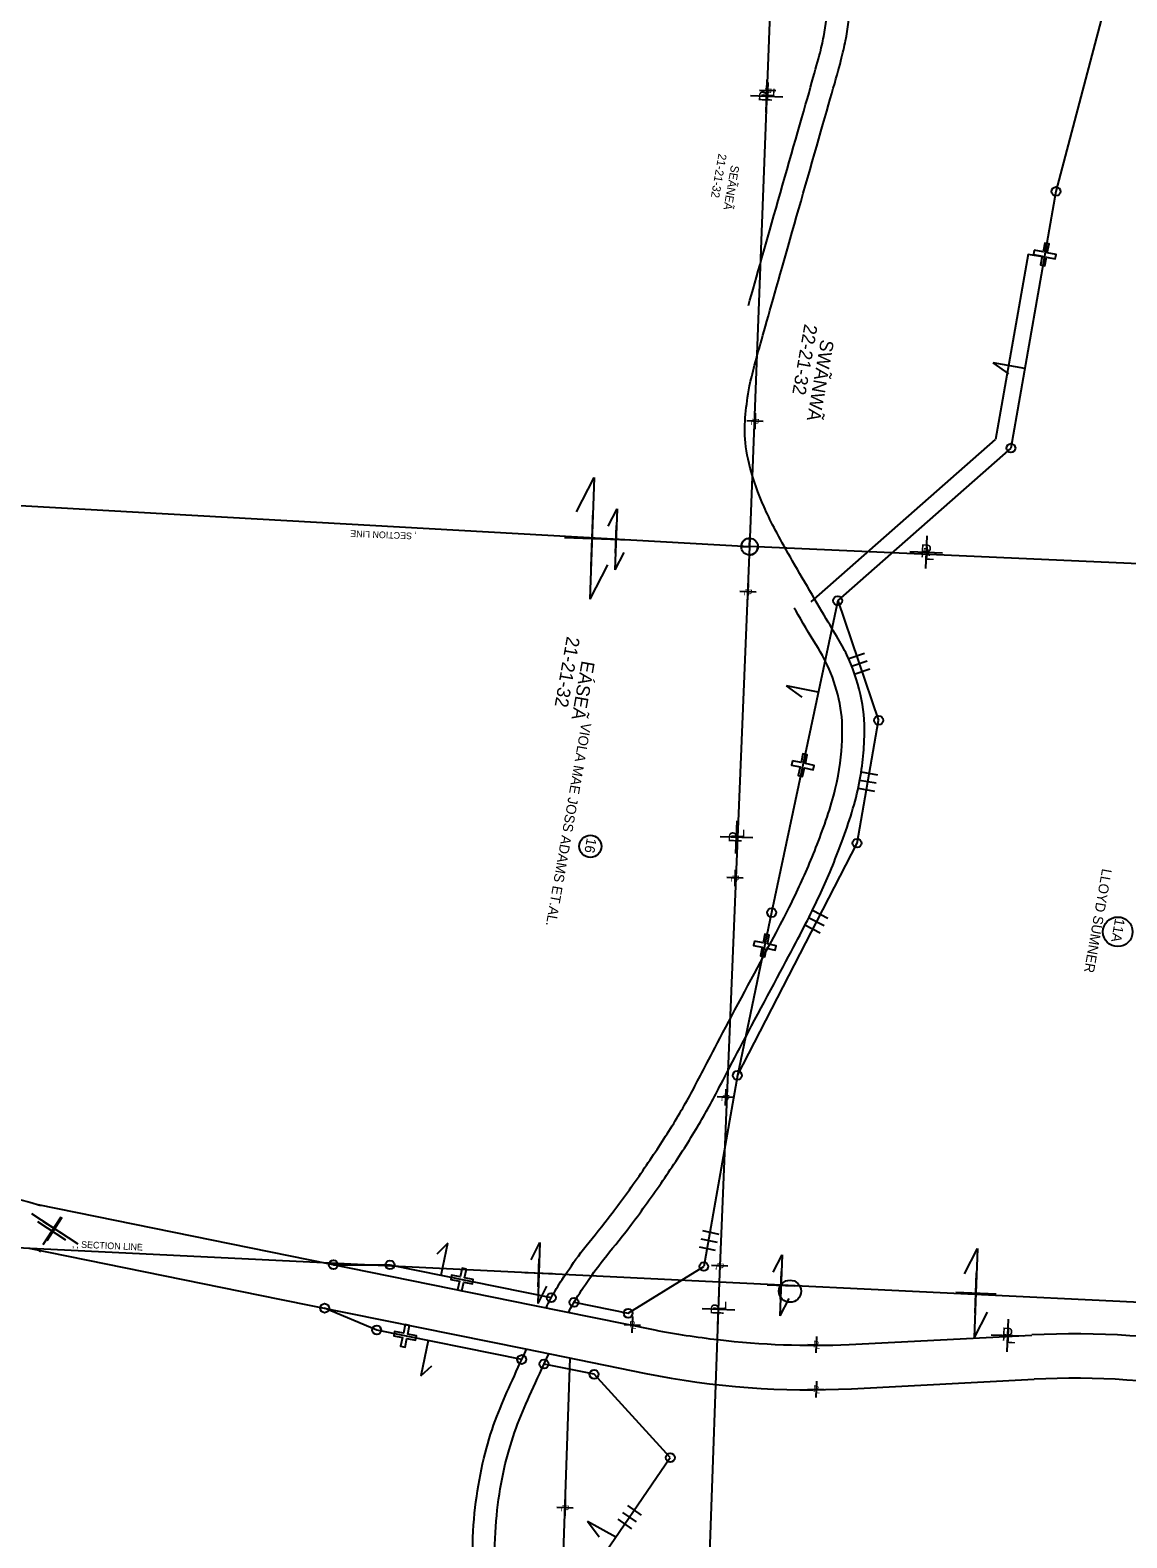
# Model space of a CAD drawing. Extents: x 2814293 to 2835768, y 121185 to 156337.
# Drawn here: x 2819450 to 2821428, y 131914 to 134634 of the extents above; entities that cross this region are included whole.
import ezdxf

# ---------------------------------------------------------------- set-up
doc = ezdxf.new("R2010")
doc.units = 0
for name, color, linetype in [('Default', 7, 'Continuous'), ('Photo-Retaining wall', 7, 'Continuous'), ('Roadway-Alignment notes', 7, 'Continuous'), ('Roadway-Ditches', 7, 'Continuous'), ('Roadway-Edge of pavement', 7, 'Continuous'), ('Roadway-Edge of shoulder', 7, 'Continuous'), ('Roadway-Entrances', 7, 'Continuous'), ('Roadway-New rw', 7, 'Continuous'), ('Roadway-Permanent easement', 7, 'Continuous'), ('Roadway-Safety', 7, 'Continuous'), ('Roadway-Walls', 7, 'Continuous'), ('Scratch-2', 7, 'Continuous'), ('Scratch-4', 7, 'Continuous'), ('Text-New rw label', 7, 'Continuous'), ('Traffic_Control-Traffic barriers', 7, 'Continuous')]:
    doc.layers.add(name, color=color, linetype=linetype)

msp = doc.modelspace()

# ---------------------------------------------------------------- linework, layer by layer
at = {"layer": 'Default'}
for p, q in [((2819451.9, 132499.4), (2819535.8, 132444.9)), ((2819513.9, 132451.6), (2819463.5, 132484.2)), ((2819505, 132493), (2819472.4, 132442.7)), ((2819472.7, 132485.5), (2819514.7, 132458.3)), ((2819480.1, 132450.9), (2819507.3, 132492.9)), ((2819466.6, 132430.2), (2819468.3, 132432.8))]:
    msp.add_line(p, q, dxfattribs=at)
at = {"layer": 'Roadway-Ditches'}
for centre, radius in [((2820460.1, 133161.8), 20), ((2821411.3, 133007.6), 26.7), ((2820820.2, 132359.3), 20)]:
    msp.add_circle(centre, radius, dxfattribs=at)
at = {"layer": 'Roadway-Edge of pavement'}
for p, q in [((2820492.2, 133739.2), (2820508.1, 133770.4)), ((2820508.1, 133770.4), (2820504.2, 133660.5)), ((2820505.2, 133690.5), (2820507, 133740.4)), ((2820481.1, 133716.3), (2820531.1, 133714.6)), ((2820506.1, 133715.4), (2820506.1, 133715.4)), ((2820520.1, 133691.6), (2820504.2, 133660.5)), ((2820353, 132416.1), (2820368.9, 132447.3)), ((2820368.9, 132447.3), (2820365, 132337.4)), ((2820789.9, 132393.5), (2820805.8, 132424.7)), ((2820805.8, 132424.7), (2820802, 132314.7)), ((2820366, 132367.3), (2820367.8, 132417.3)), ((2820341.9, 132393.2), (2820391.9, 132391.4)), ((2820366.9, 132392.3), (2820366.9, 132392.3)), ((2820778.9, 132370.6), (2820828.9, 132368.8)), ((2820803, 132344.7), (2820804.8, 132394.7)), ((2820803.9, 132369.7), (2820803.9, 132369.7)), ((2820380.9, 132368.5), (2820365, 132337.4)), ((2820817.9, 132345.9), (2820802, 132314.7))]:
    msp.add_line(p, q, dxfattribs=at)
at = {"layer": 'Roadway-Edge of shoulder'}
for p, q in [((2820777, 134485.6), (2820779, 134544.5)), ((2820748.6, 134516.1), (2820807.4, 134514)), ((2821066.8, 133722), (2821064.5, 133663.1)), ((2821036.2, 133693.7), (2821095.1, 133691.4)), ((2820722.5, 133149.1), (2820724.6, 133208)), ((2820694.1, 133179.6), (2820753, 133177.5)), ((2820690, 132297.4), (2820692.1, 132356.3)), ((2820661.6, 132327.9), (2820720.5, 132325.8)), ((2821213.5, 132309), (2821211.2, 132250.2)), ((2821182.9, 132280.8), (2821241.7, 132278.5))]:
    msp.add_line(p, q, dxfattribs=at)
at = {"layer": 'Roadway-Entrances'}
for p, q in [((2820848.6, 136362.6), (2820747.1, 133702.4)), ((2821215, 134013.9), (2821186.3, 134034)), ((2821243.7, 134023.9), (2821186.3, 134034)), ((2819128.6, 133793.8), (2820747.1, 133702.4)), ((2820747.1, 133702.4), (2820692.1, 132375.8)), ((2822068.5, 133644.1), (2820747.1, 133702.4)), ((2820842.1, 133430.6), (2820814, 133451.5)), ((2820871.1, 133439.7), (2820814, 133451.5)), ((2820692.1, 132375.8), (2818892.4, 132463.7)), ((2820203.1, 132446.2), (2820183.4, 132426)), ((2820191.2, 132388), (2820203.1, 132446.2)), ((2820692.1, 132375.8), (2820645.7, 131042.3)), ((2822012.3, 132311.3), (2820692.1, 132375.8)), ((2820167.3, 132270.4), (2820154.3, 132206.7)), ((2820154.3, 132206.7), (2820173.9, 132224.7)), ((2820475.6, 131915.7), (2820455, 131944)), ((2820506, 131915.8), (2820455, 131944))]:
    msp.add_line(p, q, dxfattribs=at)
at = {"layer": 'Roadway-New rw'}
for p, q in [((2821386.6, 134673.4), (2821299.8, 134343.2)), ((2821299.8, 134343.2), (2821218.5, 133880.2)), ((2821218.5, 133880.2), (2820906.2, 133605.1)), ((2820906.2, 133605.1), (2820787, 133042.3)), ((2820906.2, 133605.1), (2820979.9, 133389.1)), ((2820925.9, 133500.8), (2820954.3, 133510.5)), ((2820930.8, 133486.6), (2820959.2, 133496.3)), ((2820935.6, 133472.4), (2820964, 133482.1)), ((2820941, 133167.5), (2820979.9, 133389.1)), ((2820948.3, 133296.1), (2820977.8, 133290.8)), ((2820945.7, 133281.4), (2820975.2, 133276.1)), ((2820943, 133266.6), (2820972.5, 133261.3)), ((2820725.2, 132748.5), (2820941, 133167.5)), ((2820787, 133042.3), (2820725.2, 132748.5)), ((2820854.8, 133032.7), (2820881.5, 133019)), ((2820861.7, 133046.1), (2820888.4, 133032.3)), ((2820848, 133019.4), (2820874.7, 133005.7)), ((2820725.2, 132748.5), (2820664.7, 132403.8)), ((2820659.1, 132454), (2820688.5, 132447.8)), ((2820662.2, 132468.7), (2820691.6, 132462.4)), ((2820656, 132439.3), (2820685.3, 132433.1)), ((2819996.6, 132407.1), (2820098.6, 132406.8)), ((2820098.6, 132406.8), (2820389.4, 132347.7)), ((2820528.1, 132319.5), (2820664.7, 132403.8)), ((2820074.7, 132289.2), (2819980.7, 132328.7)), ((2820430.7, 132339.3), (2820528.1, 132319.5)), ((2820336.3, 132236), (2820074.7, 132289.2)), ((2820466.7, 132209.5), (2820376.5, 132227.9)), ((2820604.1, 132059.1), (2820466.7, 132209.5)), ((2820414, 131781.5), (2820604.1, 132059.1)), ((2820526.8, 131972.7), (2820551.4, 131955.5)), ((2820509.6, 131948), (2820534.2, 131930.9)), ((2820518.2, 131960.3), (2820542.8, 131943.2))]:
    msp.add_line(p, q, dxfattribs=at)
for points in [[(2821260.7, 134237.2), (2821259.2, 134229.4), (2821274.9, 134226.3), (2821271.9, 134210.6), (2821279.7, 134209.1), (2821282.7, 134224.8), (2821298.4, 134221.8), (2821300, 134229.7), (2821284.2, 134232.7), (2821287.3, 134248.4), (2821279.4, 134249.9), (2821276.4, 134234.2), (2821260.7, 134237.2)], [(2820824.4, 133316.1), (2820822.8, 133308.3), (2820838.4, 133305), (2820835.1, 133289.4), (2820842.9, 133287.7), (2820846.2, 133303.4), (2820861.9, 133300.1), (2820863.5, 133307.9), (2820847.9, 133311.2), (2820851.2, 133326.9), (2820843.4, 133328.5), (2820840.1, 133312.9), (2820824.4, 133316.1)], [(2820755.9, 132990.9), (2820754.2, 132983), (2820769.9, 132979.7), (2820766.6, 132964.1), (2820774.4, 132962.4), (2820777.7, 132978.1), (2820793.4, 132974.8), (2820795, 132982.6), (2820779.4, 132985.9), (2820782.6, 133001.6), (2820774.8, 133003.2), (2820771.5, 132987.6), (2820755.9, 132990.9)], [(2820236.4, 132399.3), (2820228.6, 132401), (2820225.4, 132385.3), (2820209.7, 132388.5), (2820208.1, 132380.7), (2820223.7, 132377.5), (2820220.5, 132361.8), (2820228.3, 132360.2), (2820231.6, 132375.8), (2820247.2, 132372.6), (2820248.9, 132380.4), (2820233.2, 132383.7), (2820236.4, 132399.3)], [(2820133.8, 132297.6), (2820125.9, 132299.2), (2820122.7, 132283.5), (2820107, 132286.8), (2820105.4, 132278.9), (2820121.1, 132275.7), (2820117.8, 132260), (2820125.7, 132258.4), (2820128.9, 132274.1), (2820144.6, 132270.8), (2820146.2, 132278.7), (2820130.5, 132281.9), (2820133.8, 132297.6)]]:
    msp.add_lwpolyline(points, close=True, dxfattribs=at)
for centre in [(2820906.2, 133605.1), (2820725.2, 132748.5), (2819996.6, 132407.1), (2820389.4, 132347.7), (2820430.6, 132339.3), (2819980.7, 132328.7), (2820336.3, 132236.1), (2820376.5, 132227.9)]:
    msp.add_circle(centre, 8.13, dxfattribs=at)
at = {"layer": 'Roadway-Permanent easement'}
for p, q in [((2821249.5, 134230.2), (2821190.7, 133895.8)), ((2821249.5, 134230.2), (2821279, 134225)), ((2820858.2, 133602.8), (2821190.7, 133895.8))]:
    msp.add_line(p, q, dxfattribs=at)
at = {"layer": 'Roadway-Walls'}
for p, q in [((2820794.3, 134524.4), (2820764.9, 134525.4)), ((2820780.1, 134539.6), (2820779.1, 134510.2)), ((2820771.6, 133928.3), (2820742.2, 133929.3)), ((2820757.4, 133943.5), (2820756.4, 133914.1)), ((2821066.2, 133707.3), (2821065.1, 133677.9)), ((2821050.9, 133693.1), (2821080.4, 133692.1)), ((2820758.9, 133620.5), (2820729.5, 133621.5)), ((2820744.7, 133635.7), (2820743.7, 133606.3)), ((2820735.6, 133104.3), (2820706.1, 133105.3)), ((2820721.4, 133119.5), (2820720.3, 133090.1)), ((2820704.2, 132723.9), (2820703.2, 132694.5)), ((2820718.4, 132708.7), (2820688.9, 132709.7)), ((2820708.1, 132404.6), (2820678.7, 132405.7)), ((2820693.9, 132419.9), (2820692.9, 132390.4)), ((2820520.9, 132299.3), (2820550.3, 132298.1)), ((2820536.2, 132313.4), (2820535, 132284)), ((2820852.4, 132263.4), (2820881.9, 132262.2)), ((2820867.7, 132277.5), (2820866.6, 132248.1)), ((2820852.4, 132182.8), (2820881.9, 132181.7)), ((2820867.7, 132197), (2820866.6, 132167.5)), ((2820429, 131968.2), (2820399.5, 131969.2)), ((2820414.8, 131983.4), (2820413.7, 131954))]:
    msp.add_line(p, q, dxfattribs=at)
at = {"layer": 'Scratch-2'}
for p, q in [((2820435.2, 133765), (2820467, 133827.3)), ((2820467, 133827.3), (2820459.3, 133607.5)), ((2820461.4, 133667.4), (2820464.9, 133767.4)), ((2820413.2, 133719.2), (2820513.2, 133715.6)), ((2820463.2, 133717.4), (2820463.2, 133717.4)), ((2820491.1, 133669.8), (2820459.3, 133607.5)), ((2821135, 132390.8), (2821158.2, 132436.3)), ((2821158.2, 132436.3), (2821152.5, 132276)), ((2821154.1, 132319.7), (2821156.6, 132392.6)), ((2821118.9, 132357.4), (2821191.8, 132354.8)), ((2821155.3, 132356.1), (2821155.3, 132356.1)), ((2821175.7, 132321.4), (2821152.5, 132276))]:
    msp.add_line(p, q, dxfattribs=at)
at = {"layer": 'Scratch-4'}
for p, q in [((2820732.2, 133702.9), (2820747.1, 133702.4)), ((2820747.1, 133702.4), (2820746.6, 133687.4)), ((2820747.1, 133702.4), (2820747.6, 133717.4)), ((2820762.1, 133701.9), (2820747.1, 133702.4))]:
    msp.add_line(p, q, dxfattribs=at)
msp.add_circle((2820747.1, 133702.4), 15, dxfattribs=at)
for start, end in [(88.1, 178.1), (268.1, 358.1)]:
    msp.add_arc((2820747.1, 133702.4), 15, start, end, dxfattribs=at)
at = {"layer": 'Text-New rw label'}
for centre in [(2821299.8, 134343.2), (2821218.5, 133880.2), (2820979.9, 133389.1), (2820941, 133167.5), (2820787, 133042.3), (2820098.6, 132406.8), (2820664.7, 132403.8), (2820528.1, 132319.5), (2820074.7, 132289.2), (2820466.7, 132209.5), (2820604.1, 132059.1)]:
    msp.add_circle(centre, 8, dxfattribs=at)
at = {"layer": 'Traffic_Control-Traffic barriers'}
for p, q in [((2820381.2, 132332.2), (2820379.7, 132329.4)), ((2820421.9, 132323.7), (2820420.4, 132321.1)), ((2820926.8, 132263.3), (2821256.2, 132280.3)), ((2820423.2, 132238.8), (2820381.9, 131053)), ((2820931, 132183.4), (2821260.3, 132200.4))]:
    msp.add_line(p, q, dxfattribs=at)
for points in [[(2819463.2, 132515.5), (2819915.5, 132423.6), (2820356.1, 132334.1), (2820576.1, 132289.4)], [(2819447.3, 132437.1), (2819899.5, 132345.2), (2820340.1, 132255.7), (2820560.2, 132211)]]:
    msp.add_lwpolyline(points, dxfattribs=at)
for centre, radius, start, end in [((2820859.3, 133762.4), 1500, 259.1198, 263.5201), ((2820861.2, 133700.7), 1438.9, 263.1664, 272.6134), ((2821332.7, 130802.8), 1479.6, 79.2581, 92.9636), ((2820854.4, 133659.1), 1477.7, 258.5159, 272.9688), ((2821332.7, 130802.8), 1399.5, 79.2583, 92.9634)]:
    msp.add_arc(centre, radius, start, end, dxfattribs=at)
for points in [[(2820745, 134137.3), (2820759.2, 134187.4), (2820796.5, 134319.8), (2820866, 134561), (2820882.3, 134622.2), (2820890.5, 134685.3), (2820890.5, 134756.7), (2820883.9, 134860.9), (2820877.2, 134984), (2820874.1, 135053.3), (2820875.7, 135099.8), (2820890.4, 135198), (2820908.8, 135318.4), (2820918.2, 135358.7), (2820947.2, 135415), (2820971.2, 135442.6), (2820998.7, 135473.5), (2821025.3, 135502.5), (2821045.1, 135531.8), (2821070.8, 135598.4), (2821079.3, 135649.1), (2821097, 135745.4), (2821119.8, 135882.3), (2821158.7, 136055), (2821178.4, 136223.5), (2821188.3, 136310.9), (2821206, 136399.5), (2821239.2, 136501.5), (2821280.2, 136573.3), (2821318.6, 136629.4), (2821360.8, 136683.1), (2821415, 136745), (2821441.8, 136778.8), (2821466.2, 136818.9), (2821496.5, 136874.2), (2821527.4, 136933.2), (2821577.1, 137015.9), (2821617.9, 137081.8), (2821646.4, 137114.1), (2821689.7, 137146.1), (2821742.9, 137169.7), (2821819.5, 137196), (2821916.7, 137230), (2821964, 137251.9), (2821999.5, 137272.8), (2822036.2, 137299.3), (2822066.7, 137332.1), (2822140.5, 137422.7), (2822185.2, 137482.3), (2822198.9, 137509), (2822215.2, 137563.4), (2822229.1, 137614.9), (2822248, 137660.6), (2822266.7, 137699.3), (2822292.7, 137735.3), (2822310.6, 137759.8), (2822332.2, 137793.7), (2822385.8, 137897), (2822427.2, 137981.4), (2822444, 138030.2), (2822454.4, 138055.9), (2822465.5, 138103.9), (2822468, 138144.1), (2822470.8, 138205.9), (2822474.8, 138257), (2822483.6, 138296.3), (2822497, 138347.3), (2822557.6, 138490), (2822586.2, 138571.2), (2822602.9, 138636.9), (2822615, 138753.6), (2822619.1, 138791.9)], [(2820421.9, 132323.7), (2820430.3, 132339.5), (2820446.6, 132365.4), (2820477.5, 132409.8), (2820521.7, 132462.2), (2820581.9, 132544.8), (2820633.7, 132622.6), (2820678.7, 132698.5), (2820711.5, 132765.4), (2820823.8, 132974.3), (2820869.5, 133062.1), (2820906.1, 133146.6), (2820945.5, 133258.7), (2820956.4, 133356.9), (2820952.7, 133425), (2820927.9, 133503.2), (2820893.9, 133557.3), (2820809, 133702.5), (2820771.2, 133774.3), (2820745.5, 133846.6), (2820736.3, 133904.7), (2820741, 133953.4), (2820747.2, 134000.7), (2820776.6, 134101.6), (2820833.7, 134304.6), (2820904.5, 134550.3), (2820921.6, 134614.4), (2820930.5, 134682.7), (2820930.5, 134758), (2820923.8, 134863.3), (2820917.2, 134986), (2820914.2, 135053.6), (2820915.6, 135096.1), (2820930, 135192), (2820948.1, 135310.8), (2820956, 135344.7), (2820980.6, 135392.4), (2821001.2, 135416.1), (2821028.4, 135446.7), (2821056.8, 135477.7), (2821080.7, 135513.2), (2821109.6, 135587.8), (2821118.7, 135642.2), (2821136.4, 135738.5), (2821159.1, 135874.6), (2821198.2, 136048.3), (2821218.1, 136218.9), (2821227.9, 136304.7), (2821244.8, 136389.4), (2821276, 136485.3), (2821314.1, 136552.1), (2821350.9, 136605.8), (2821391.6, 136657.6), (2821445.7, 136719.4), (2821474.7, 136755.9), (2821500.8, 136798.9), (2821531.8, 136855.4), (2821562.3, 136913.6), (2821611.3, 136995.1), (2821650.2, 137057.9), (2821673.5, 137084.5), (2821709.9, 137111.3), (2821757.5, 137132.5), (2821832.5, 137158.2), (2821931.7, 137192.9), (2821982.6, 137216.4), (2822021.4, 137239.3), (2822062.8, 137269.2), (2822096.8, 137305.8), (2822172, 137398.1), (2822219.2, 137461.1), (2822236.1, 137494), (2822253.7, 137552.5), (2822267, 137602), (2822284.6, 137644.3), (2822301.1, 137678.7), (2822325.1, 137711.8), (2822343.7, 137737.3), (2822366.9, 137773.8), (2822421.5, 137879), (2822464.2, 137966.1), (2822481.4, 138016.2), (2822492.6, 138043.8), (2822505.3, 138098.1), (2822507.9, 138141.9), (2822510.7, 138203.4), (2822514.5, 138251), (2822522.5, 138286.8), (2822534.9, 138334.4), (2822594.9, 138475.5), (2822624.6, 138559.6), (2822642.4, 138629.9), (2822654.8, 138749.4), (2822658.9, 138787.6)], [(2816475.6, 136152.5), (2816815.6, 136256.7), (2816969.1, 135990.5), (2817030.3, 135813.1), (2817217.9, 135593.4), (2817584.6, 135335.9), (2817692.5, 135093.9), (2817881, 134760.4), (2817921.5, 134518.9), (2817861.6, 134296.4), (2817832.5, 134124.1), (2817795.2, 133986.7), (2817866.7, 133777.8), (2817992.3, 133674.1), (2818253, 133548.5), (2818528.3, 133349.4), (2818833.6, 132888.1), (2818987.7, 132759.8), (2819135.1, 132625.3), (2819254, 132573.4), (2819468.6, 132514.2)], [(2820381.2, 132332.2), (2820382.8, 132335.2), (2820393.7, 132356.4), (2820412.9, 132386.9), (2820445.8, 132434.2), (2820490.2, 132486.9), (2820549.1, 132567.7), (2820599.9, 132643.9), (2820643.5, 132717.5), (2820676, 132783.7), (2820788.4, 132993), (2820833.4, 133079.3), (2820868.8, 133161.2), (2820906.2, 133267.7), (2820916.2, 133358), (2820913, 133417.8), (2820891.3, 133486.2), (2820866.5, 133525.7), (2820835.9, 133577.5), (2820827.6, 133591.7)], [(2820289.4, 131538), (2820248.4, 131835.6), (2820245.9, 131907.1), (2820253.9, 131990.2), (2820268.9, 132068.3), (2820290.8, 132135), (2820315.3, 132190.2), (2820334.7, 132232.6), (2820344.9, 132254.7)], [(2820329, 131543.4), (2820288.3, 131839), (2820286, 131905.9), (2820293.5, 131984.5), (2820307.7, 132058.2), (2820328.2, 132120.6), (2820352.8, 132176.2), (2820373.7, 132221.8), (2820385.2, 132246.5)]]:
    msp.add_open_spline(points, degree=3, dxfattribs=at)

# ---------------------------------------------------------------- texts
at = {"layer": 'Photo-Retaining wall'}
for s, p in [('21-21-32', (2820691.3, 134412.1)), ('SEÃNEÃ', (2820714, 134391.3))]:
    msp.add_text(s, height=15, rotation=260.038, dxfattribs=at).set_placement(p)
at = {"layer": 'Roadway-Alignment notes'}
for s, p in [('22-21-32', (2820846.3, 134105)), ('SWÃNWÃ', (2820875.9, 134077)), ('21-21-32', (2820417.7, 133541.4)), ('EÁSEÃ', (2820444.5, 133497.6))]:
    msp.add_text(s, height=24, rotation=260.038, dxfattribs=at).set_placement(p)
at = {"layer": 'Roadway-Ditches'}
for s, p in [('VIOLA MAE JOSS ADAMS ET.AL.', (2820444, 133385.5)), ('16', (2820453.8, 133177.8)), ('LLOYD SUMNER', (2821383.1, 133122.4)), ('11A', (2821406.6, 133032.8))]:
    msp.add_text(s, height=18, rotation=260.038, dxfattribs=at).set_placement(p)
at = {"layer": 'Roadway-Edge of shoulder'}
for s, rotation, p in [('P', 87.9775, (2820787.2, 134504)), ('L', 87.9775, (2820791.8, 134511.9)), ('P', 357.7804, (2821054.6, 133683.4)), ('L', 357.7804, (2821062.4, 133678.8)), ('P', 87.9775, (2820732.8, 133167.5)), ('L', 87.9775, (2820737.4, 133175.4)), ('P', 87.9775, (2820700.3, 132315.8)), ('L', 87.9775, (2820704.9, 132323.7)), ('P', 357.7804, (2821201.3, 132270.4)), ('L', 357.7804, (2821209.1, 132265.8))]:
    msp.add_text(s, height=23.6, rotation=rotation, dxfattribs=at).set_placement(p)
at = {"layer": 'Roadway-Safety'}
for s, rotation, p in [('‚ SECTION LINE', 177.7804, (2820146.6, 133727.3)), ('‚ ‚ SECTION LINE', 357.3804, (2819525.3, 132438.4))]:
    msp.add_text(s, height=12, rotation=rotation, dxfattribs=at).set_placement(p)
at = {"layer": 'Roadway-Walls'}
for s, rotation, p in [('L', 267.9775, (2820772.7, 134526.5)), ('P', 267.9775, (2820775, 134530.4)), ('L', 267.9775, (2820750, 133930.4)), ('P', 267.9775, (2820752.3, 133934.3)), ('P', 357.9775, (2821060.1, 133688)), ('L', 357.9775, (2821064.1, 133685.7)), ('L', 267.9775, (2820737.3, 133622.6)), ('P', 267.9775, (2820739.6, 133626.5)), ('L', 267.9775, (2820713.9, 133106.4)), ('P', 267.9775, (2820716.2, 133110.3)), ('L', 267.9775, (2820696.8, 132710.8)), ('P', 267.9775, (2820699, 132714.7)), ('L', 267.9775, (2820686.5, 132406.7)), ('P', 267.9775, (2820688.8, 132410.7)), ('P', 357.7804, (2820530.1, 132294.1)), ('L', 357.7804, (2820534, 132291.8)), ('P', 357.7804, (2820861.6, 132258.2)), ('L', 357.7804, (2820865.5, 132255.9)), ('P', 357.7804, (2820861.6, 132177.6)), ('L', 357.7804, (2820865.5, 132175.3)), ('L', 267.9775, (2820407.3, 131970.3)), ('P', 267.9775, (2820409.6, 131974.2))]:
    msp.add_text(s, height=11.8, rotation=rotation, dxfattribs=at).set_placement(p)

doc.saveas('drawing.dxf')
